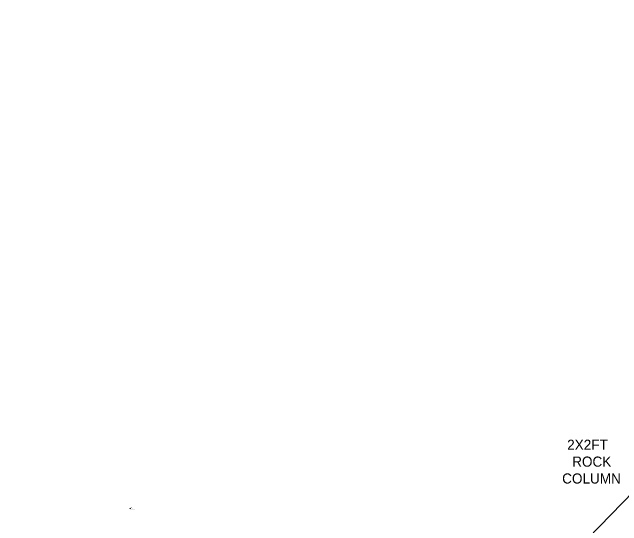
# Model space of a CAD drawing. Extents: x 2250985 to 2256614, y 13788366 to 13792478.
# Drawn here: x 2253199.8 to 2253272, y 13789153.5 to 13789214.4 of the extents above; entities that cross this region are included whole.
import ezdxf

# ---------------------------------------------------------------- set-up
doc = ezdxf.new("R2010")
doc.units = 0
for name, color, linetype in [('BORD_legend_int', 7, 'Continuous'), ('BORD_legend_plan_prof_screen', 7, 'Continuous'), ('BORD_legend_TCP', 7, 'Continuous'), ('BORD_legend_TCP_screen', 7, 'Continuous'), ('E_ROW_Driveway_3D_R', 7, 'Continuous'), ('E_Struc_Misc', 7, 'Continuous'), ('E_Terrain_Triangle_Vertices', 7, 'Continuous')]:
    doc.layers.add(name, color=color, linetype=linetype)

# ---------------------------------------------------------------- blocks, each defined once
blk = doc.blocks.new('NG')
at = {"layer": 'BORD_legend_plan_prof_screen'}
for p in [(-0.07, 0.09), (-0.07, -0.09), (0.07, 0.09), (0.07, -0.09)]:
    blk.add_line(p, (0, 0), dxfattribs=at)

msp = doc.modelspace()

# ---------------------------------------------------------------- linework, layer by layer
at = {"layer": 'E_ROW_Driveway_3D_R'}
for points in [[(2253258.7, 13789125.01), (2253285.19, 13789150.8), (2253358.83, 13789226.99), (2253433.23, 13789304.07), (2253504.79, 13789378.92), (2253542.21, 13789416.41), (2253558.99, 13789436.05)], [(2253199.79, 13789023.57), (2253231.26, 13789055.67), (2253305.08, 13789131.6), (2253378.64, 13789207.45), (2253453.2, 13789283.87)]]:
    msp.add_spline(points, degree=3, dxfattribs=at)
at = {"layer": 'E_Struc_Misc'}
msp.add_lwpolyline([(2253248.77, 13789132.2), (2253276.19, 13789160.46), (2253350.01, 13789235.98), (2253424.99, 13789312.95), (2253496.37, 13789386.32), (2253548.6, 13789439.77)], dxfattribs=at)

# ---------------------------------------------------------------- block references
at = {"layer": 'BORD_legend_plan_prof_screen', "xscale": 0.5, "yscale": 0.5}
msp.add_blockref('NG', (2253213.76, 13789155.56), dxfattribs=at)

# ---------------------------------------------------------------- texts
at = {"layer": 'BORD_legend_int'}
msp.add_text('NATURAL GROUND', height=0.06, dxfattribs=at).set_placement((2253213.82, 13789155.44))
at = {"layer": 'BORD_legend_TCP'}
msp.add_text('6695', height=0.06, dxfattribs=at).set_placement((2253213.82, 13789155.62))
at = {"layer": 'BORD_legend_TCP_screen'}
msp.add_text('661.84', height=0.06, dxfattribs=at).set_placement((2253213.82, 13789155.53))
at = {"layer": 'E_Terrain_Triangle_Vertices'}
for s, p in [('2X2FT ', (2253265.534, 13789162.507)), ('ROCK ', (2253266.127, 13789160.507)), ('COLUMN', (2253264.942, 13789158.507))]:
    msp.add_text(s, height=1.2, dxfattribs=at).set_placement(p)

doc.saveas('drawing.dxf')
